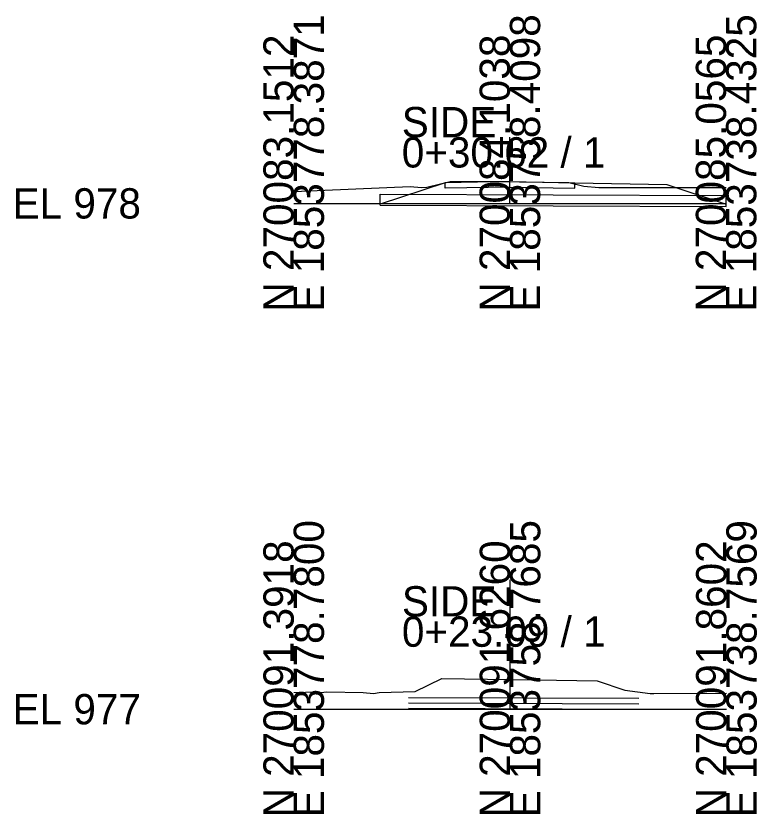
# Model space of a CAD drawing. Extents: x -26 to 60, y -10 to 517.
# Drawn here: x -25.7 to 42.9, y 443.5 to 517.3 of the extents above; entities that cross this region are included whole.
import ezdxf

# ---------------------------------------------------------------- set-up
doc = ezdxf.new("R2010")
doc.units = 0
for name, color, linetype in [('DR_P_Drive_Pipe', 7, 'Continuous'), ('GK_Cells', 7, 'Continuous'), ('XS_P_Finished_Grade', 7, 'Continuous'), ('XS_X_Ground_Line', 7, 'Continuous')]:
    doc.layers.add(name, color=color, linetype=linetype)

msp = doc.modelspace()

# ---------------------------------------------------------------- linework, layer by layer
at = {"layer": 'DR_P_Drive_Pipe'}
for p, q in [((8, 500.841), (40, 500.718)), ((8, 499.841), (8, 500.841)), ((40, 499.718), (40, 500.718)), ((8, 499.841), (40, 499.718))]:
    msp.add_line(p, q, dxfattribs=at)
at = {"layer": 'GK_Cells'}
for p, q in [((20, 500), (20, 506.115)), ((0, 500), (20, 500)), ((20, 500), (40, 500)), ((20.013, 453.241), (20.013, 461.812)), ((0, 453.241), (20.013, 453.241)), ((20.013, 453.241), (40.026, 453.241))]:
    msp.add_line(p, q, dxfattribs=at)
at = {"layer": 'XS_P_Finished_Grade'}
for p, q in [((14, 501.913), (8, 499.913)), ((20, 502.009), (14, 501.913)), ((14, 501.413), (14, 501.913)), ((20, 502.009), (26, 501.913)), ((26, 501.413), (26, 501.913)), ((26, 501.913), (34.521, 501.739)), ((34.521, 501.739), (40, 499.913)), ((20, 501.509), (14, 501.413)), ((20, 501.509), (26, 501.413)), ((20.013, 453.241), (20.013, 465.191)), ((10.621, 454.327), (31.936, 454.245)), ((10.621, 453.827), (31.936, 453.745)), ((0, 453.241), (40.026, 453.241)), ((10.621, 453.327), (31.936, 453.245))]:
    msp.add_line(p, q, dxfattribs=at)
at = {"layer": 'XS_X_Ground_Line'}
for points in [[(0, 501.11), (10.78, 501.555), (11.826, 501.478), (12.309, 501.491), (14.479, 502.038), (20, 502.009), (20.891, 502.004), (25.463, 501.923), (26.843, 501.591), (28.219, 501.47), (37.971, 501.472), (38.643, 501.471), (40, 501.468)], [(0, 454.79), (2.147, 454.842), (2.504, 454.783), (3.059, 454.842), (6.43, 454.771), (7.377, 454.704), (7.922, 454.777), (11.235, 454.883), (13.72, 456.091), (20.013, 455.989), (22.437, 455.947), (28.08, 455.859), (30.619, 455.005), (32.98, 454.7), (33.327, 454.695), (40.026, 454.731)]]:
    msp.add_lwpolyline(points, dxfattribs=at)

# ---------------------------------------------------------------- texts
at = {"layer": 'GK_Cells'}
for s, p in [('E 1853778.3871', (2.8, 490)), ('E 1853758.4098', (22.8, 490)), ('E 1853738.4325', (42.8, 490)), ('N 270083.1512', (0, 490)), ('N 270084.1038', (20, 490)), ('N 270085.0565', (40, 490)), ('E 1853778.7800', (2.8, 443.241)), ('E 1853758.7685', (22.813, 443.241)), ('E 1853738.7569', (42.826, 443.241)), ('N 270091.3918', (0, 443.241)), ('N 270091.6260', (20.013, 443.241)), ('N 270091.8602', (40.026, 443.241))]:
    msp.add_text(s, height=2.8, rotation=90, dxfattribs=at).set_placement(p)
for s, p in [('SIDE', (10, 506.115)), ('0+30.62 / 1', (10, 503.315)), ('EL 978', (-26, 498.6)), ('SIDE', (10.013, 461.812)), ('0+23.09 / 1', (10.013, 459.012)), ('EL 977', (-26, 451.841))]:
    msp.add_text(s, height=2.8, dxfattribs=at).set_placement(p)

doc.saveas('drawing.dxf')
